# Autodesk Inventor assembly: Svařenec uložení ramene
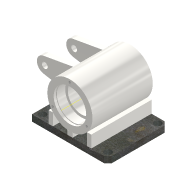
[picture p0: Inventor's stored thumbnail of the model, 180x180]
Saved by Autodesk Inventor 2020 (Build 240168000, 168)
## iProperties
Created: 2025-03
Part Number: Svařenec uložení ramene
Document SubType Name: Assembly
Designer: doma
Mass: 4743.34 g
Surface Area: 1118.38 cm^2
Volume: 604.247 cm^3
Density: 7.85 g/cm^3
Author: doma
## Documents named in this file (6)
- C:\Users\doma\Desktop\Pásovka záloha\Workgroups\NotInProject\Svařenec uložení ramene.iam
- C:\Users\doma\Desktop\Pásovka záloha\Workgroups\NotInProject\Uložení ramene.ipt
- C:\Users\doma\Desktop\Pásovka záloha\Workgroups\NotInProject\Deska uložení ramene.ipt
- C:\Users\doma\Desktop\Pásovka záloha\Workgroups\NotInProject\Výztuha uložení ramene.ipt
- C:\Users\doma\Desktop\Pásovka záloha\Workgroups\NotInProject\Držák válce.ipt
- C:\Users\doma\Desktop\Pásovka záloha\Workgroups\NotInProject\Podstava uložení čepu.ipt
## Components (7 placed, 5 different names)
1. Uložení ramene:1 — Stejný směr:1, Stejný směr:2, Tečnost:2, Tečnost:3, Proti sobě:4, Proti sobě:8, Tečnost:4
2. Deska uložení ramene:1 — Stejný směr:1, Stejný směr:2, Proti sobě:1, Proti sobě:2, Stejný směr:3, Stejný směr:4, Úhel:1, Stejný směr:5, Proti sobě:7, Stejný směr:6
3. Výztuha uložení ramene:1 — Proti sobě:1, Stejný směr:4, Tečnost:2
4. Výztuha uložení ramene:2 — Proti sobě:2, Stejný směr:3, Tečnost:3
5. Držák válce:1 — Proti sobě:3, Proti sobě:4, Proti sobě:5, Proti sobě:6, Úhel:1, Stejný směr:5
6. Držák válce:2 — Proti sobě:3, Proti sobě:5, Proti sobě:6
7. Podstava uložení čepu:1 — Proti sobě:7, Stejný směr:6, Proti sobě:8, Tečnost:4
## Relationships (18: Mate 8, Flush 6, Tangent 3, Angle 1)
- Stejný směr:1 [Flush]: Uložení ramene:1 ↔ Deska uložení ramene:1
- Stejný směr:2 [Flush]: Uložení ramene:1 ↔ Deska uložení ramene:1
- Proti sobě:1 [Mate]: Deska uložení ramene:1 ↔ Výztuha uložení ramene:1
- Proti sobě:2 [Mate]: Deska uložení ramene:1 ↔ Výztuha uložení ramene:2
- Stejný směr:3 [Flush]: Deska uložení ramene:1 ↔ Výztuha uložení ramene:2
- Stejný směr:4 [Flush]: Deska uložení ramene:1 ↔ Výztuha uložení ramene:1
- Tečnost:2 [Tangent]: Uložení ramene:1 ↔ Výztuha uložení ramene:1
- Tečnost:3 [Tangent]: Uložení ramene:1 ↔ Výztuha uložení ramene:2
- Proti sobě:3 [Mate]: Držák válce:1 ↔ Držák válce:2
- Proti sobě:4 [Mate]: Uložení ramene:1 ↔ Držák válce:1
- Proti sobě:5 [Mate]: Držák válce:1 ↔ Držák válce:2
- Proti sobě:6 [Mate]: Držák válce:1 ↔ Držák válce:2
- Úhel:1 [Angle]: Deska uložení ramene:1 ↔ Držák válce:1
- Stejný směr:5 [Flush]: Deska uložení ramene:1 ↔ Držák válce:1
- Proti sobě:7 [Mate]: Deska uložení ramene:1 ↔ Podstava uložení čepu:1
- Stejný směr:6 [Flush]: Deska uložení ramene:1 ↔ Podstava uložení čepu:1
- Proti sobě:8 [Mate]: Uložení ramene:1 ↔ Podstava uložení čepu:1
- Tečnost:4 [Tangent]: Uložení ramene:1 ↔ Podstava uložení čepu:1
